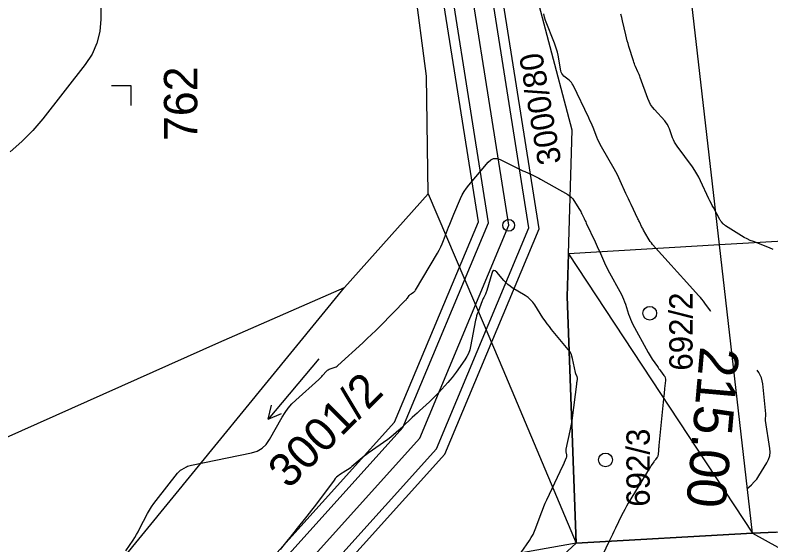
# Model space of a CAD drawing. Extents: x -534481 to -534262, y -1190577 to -1190138.
# Drawn here: x -534403.93 to -534384.66, y -1190505.1 to -1190491.61 of the extents above; entities that cross this region are included whole.
import ezdxf

# ---------------------------------------------------------------- set-up
doc = ezdxf.new("R2010")
doc.units = 0
for name, color, linetype in [('Bonity', 7, 'Continuous'), ('Definiční body', 7, 'Continuous'), ('Polygon budovy', 7, 'Continuous'), ('Polygon parcely', 7, 'Continuous'), ('Vrstva 17', 7, 'Continuous'), ('Vrstva 18', 7, 'Continuous'), ('Vrstva 19', 7, 'Continuous'), ('Vrstva 35', 7, 'Continuous'), ('Vrstva 37', 7, 'Continuous'), ('Vrstva 46', 7, 'Continuous'), ('Vrstva 48', 7, 'Continuous')]:
    doc.layers.add(name, color=color, linetype=linetype)

msp = doc.modelspace()

# ---------------------------------------------------------------- linework, layer by layer
at = {"layer": 'Bonity'}
msp.add_lwpolyline([(-534408.105, -1190518.46), (-534393.616, -1190502.389), (-534391.346, -1190496.962), (-534392.763, -1190488.017), (-534396.655, -1190477.752), (-534402.513, -1190464.283), (-534404.757, -1190456.741), (-534408.311, -1190433.088), (-534409.248, -1190427.879), (-534409.316, -1190416.054), (-534409.076, -1190409.418), (-534409.868, -1190391.439)], dxfattribs=at)
at = {"layer": 'Definiční body'}
for p, q in [((-534395.53, -1190498.55), (-534393.4, -1190496.16)), ((-534389.82, -1190497.69), (-534385.13, -1190504.81)), ((-534402.95, -1190507.61), (-534395.53, -1190498.55)), ((-534385.13, -1190504.81), (-534389.63, -1190505.06)), ((-534384.53, -1190504.78), (-534385.13, -1190504.81)), ((-534389.63, -1190505.06), (-534401.56, -1190515.98))]:
    msp.add_line(p, q, dxfattribs=at)
for points in [[(-534385.13, -1190504.81), (-534385.97, -1190497.46), (-534387.18, -1190486.94)], [(-534389.82, -1190497.69), (-534389.73, -1190494.54), (-534391.64, -1190487.29)], [(-534393.4, -1190496.16), (-534393.44, -1190493.16), (-534393.76, -1190490.76)], [(-534393.4, -1190496.16), (-534392, -1190499.45), (-534391.5, -1190500.63), (-534389.63, -1190505.06)], [(-534389.63, -1190505.06), (-534389.86, -1190498.78), (-534389.82, -1190497.69)], [(-534404.16, -1190502.37), (-534398.74, -1190499.95), (-534395.53, -1190498.55)], [(-534385.13, -1190504.81), (-534384.49, -1190505.16), (-534382.4, -1190506.3), (-534375.507, -1190510.084)], [(-534389.63, -1190505.06), (-534396.5, -1190506.28), (-534398.08, -1190506.56), (-534402.44, -1190507.34), (-534402.95, -1190507.61)]]:
    msp.add_lwpolyline(points, dxfattribs=at)
at = {"layer": 'Polygon parcely'}
msp.add_lwpolyline([(-534381.11, -1190486.74), (-534379.63, -1190494.14), (-534379.04, -1190497.06), (-534379.33, -1190497.08), (-534385.97, -1190497.46), (-534389.82, -1190497.69), (-534389.86, -1190498.78), (-534389.63, -1190505.06), (-534385.13, -1190504.81), (-534384.53, -1190504.78), (-534372.8, -1190504.12), (-534374.01, -1190497.07), (-534374.08, -1190496.69), (-534374.94, -1190492.52), (-534375.06, -1190491.94), (-534376.48, -1190486.28), (-534380.38, -1190486.72)], close=True, dxfattribs=at)
at = {"layer": 'Vrstva 18'}
for points in [[(-534384.605, -1190497.576), (-534384.698, -1190497.535), (-534385.11, -1190497.378), (-534385.189, -1190497.346), (-534385.267, -1190497.31), (-534385.342, -1190497.27), (-534385.416, -1190497.226), (-534385.821, -1190496.973), (-534385.836, -1190496.962), (-534385.85, -1190496.951), (-534385.864, -1190496.939), (-534385.876, -1190496.926), (-534385.925, -1190496.872), (-534385.937, -1190496.858), (-534385.947, -1190496.843), (-534385.957, -1190496.828), (-534385.966, -1190496.812), (-534386.129, -1190496.51), (-534386.159, -1190496.454), (-534386.188, -1190496.397), (-534386.216, -1190496.341), (-534386.243, -1190496.283), (-534386.454, -1190495.832), (-534386.5, -1190495.739), (-534386.551, -1190495.649), (-534386.606, -1190495.561), (-534386.665, -1190495.476), (-534387.056, -1190494.942), (-534387.09, -1190494.892), (-534387.12, -1190494.84), (-534387.146, -1190494.787), (-534387.168, -1190494.731), (-534387.249, -1190494.504), (-534387.272, -1190494.449), (-534387.299, -1190494.397), (-534387.332, -1190494.348), (-534387.37, -1190494.302), (-534387.63, -1190494.015), (-534387.683, -1190493.95), (-534387.729, -1190493.881), (-534387.768, -1190493.808), (-534387.801, -1190493.73), (-534387.995, -1190493.194), (-534388.008, -1190493.158), (-534388.022, -1190493.123), (-534388.037, -1190493.088), (-534388.052, -1190493.053), (-534388.114, -1190492.914), (-534388.13, -1190492.879), (-534388.144, -1190492.844), (-534388.156, -1190492.808), (-534388.168, -1190492.772), (-534388.282, -1190492.406), (-534388.304, -1190492.333), (-534388.325, -1190492.259), (-534388.344, -1190492.185), (-534388.362, -1190492.11), (-534388.443, -1190491.752), (-534388.464, -1190491.668), (-534388.488, -1190491.585)], [(-534401.104, -1190505.256), (-534400.924, -1190504.982), (-534400.88, -1190504.913), (-534400.838, -1190504.842), (-534400.797, -1190504.771), (-534400.758, -1190504.699), (-534400.552, -1190504.308), (-534400.504, -1190504.22), (-534400.451, -1190504.134), (-534400.394, -1190504.051), (-534400.334, -1190503.97), (-534399.786, -1190503.274), (-534399.763, -1190503.248), (-534399.739, -1190503.225), (-534399.712, -1190503.204), (-534399.683, -1190503.186), (-534399.563, -1190503.118), (-534399.533, -1190503.102), (-534399.502, -1190503.089), (-534399.469, -1190503.079), (-534399.436, -1190503.07), (-534397.901, -1190502.759), (-534397.758, -1190502.714), (-534397.633, -1190502.644), (-534397.528, -1190502.547), (-534397.442, -1190502.423), (-534397.122, -1190501.852), (-534397.048, -1190501.732), (-534396.965, -1190501.619), (-534396.873, -1190501.513), (-534396.772, -1190501.415), (-534396.19, -1190500.891), (-534396.165, -1190500.868), (-534396.14, -1190500.843), (-534396.115, -1190500.818), (-534396.092, -1190500.792), (-534395.989, -1190500.676), (-534395.969, -1190500.657), (-534395.948, -1190500.642), (-534395.925, -1190500.629), (-534395.9, -1190500.62), (-534395.795, -1190500.588), (-534395.77, -1190500.579), (-534395.746, -1190500.567), (-534395.724, -1190500.552), (-534395.703, -1190500.535), (-534395.065, -1190499.954), (-534394.953, -1190499.85), (-534394.842, -1190499.745), (-534394.733, -1190499.638), (-534394.625, -1190499.53), (-534393.978, -1190498.871), (-534393.965, -1190498.858), (-534393.952, -1190498.844), (-534393.941, -1190498.829), (-534393.929, -1190498.815), (-534393.883, -1190498.754), (-534393.872, -1190498.741), (-534393.86, -1190498.728), (-534393.846, -1190498.717), (-534393.832, -1190498.707), (-534393.773, -1190498.668), (-534393.759, -1190498.657), (-534393.746, -1190498.646), (-534393.735, -1190498.632), (-534393.725, -1190498.618), (-534393.164, -1190497.67), (-534393.12, -1190497.592), (-534393.079, -1190497.512), (-534393.042, -1190497.431), (-534393.009, -1190497.348), (-534392.882, -1190497.012), (-534392.85, -1190496.929), (-534392.816, -1190496.845), (-534392.782, -1190496.762), (-534392.748, -1190496.68), (-534392.576, -1190496.28), (-534392.533, -1190496.188), (-534392.483, -1190496.1), (-534392.426, -1190496.016), (-534392.363, -1190495.936), (-534391.869, -1190495.353), (-534391.803, -1190495.293), (-534391.731, -1190495.262), (-534391.652, -1190495.261), (-534391.568, -1190495.289), (-534391.142, -1190495.497), (-534391.091, -1190495.522), (-534391.041, -1190495.546), (-534390.99, -1190495.57), (-534390.938, -1190495.593), (-534390.733, -1190495.686), (-534390.682, -1190495.709), (-534390.632, -1190495.734), (-534390.582, -1190495.76), (-534390.533, -1190495.787), (-534389.84, -1190496.179), (-534389.794, -1190496.209), (-534389.753, -1190496.244), (-534389.716, -1190496.284), (-534389.685, -1190496.328), (-534389.544, -1190496.557), (-534389.528, -1190496.585), (-534389.512, -1190496.613), (-534389.497, -1190496.641), (-534389.482, -1190496.67), (-534389.426, -1190496.786), (-534389.412, -1190496.815), (-534389.398, -1190496.845), (-534389.384, -1190496.874), (-534389.37, -1190496.903), (-534389.145, -1190497.38), (-534389.117, -1190497.439), (-534389.09, -1190497.499), (-534389.063, -1190497.559), (-534389.036, -1190497.619), (-534388.931, -1190497.86), (-534388.905, -1190497.92), (-534388.876, -1190497.979), (-534388.847, -1190498.038), (-534388.816, -1190498.096), (-534388.475, -1190498.727), (-534388.445, -1190498.787), (-534388.418, -1190498.847), (-534388.393, -1190498.909), (-534388.372, -1190498.972), (-534388.291, -1190499.226), (-534388.27, -1190499.288), (-534388.245, -1190499.35), (-534388.218, -1190499.411), (-534388.188, -1190499.47), (-534387.79, -1190500.206), (-534387.766, -1190500.249), (-534387.741, -1190500.291), (-534387.714, -1190500.333), (-534387.686, -1190500.374), (-534387.557, -1190500.559), (-534387.536, -1190500.588), (-534387.516, -1190500.617), (-534387.495, -1190500.646), (-534387.474, -1190500.674), (-534387.389, -1190500.788), (-534387.371, -1190500.817), (-534387.359, -1190500.848), (-534387.353, -1190500.881), (-534387.353, -1190500.915), (-534387.372, -1190501.117), (-534387.376, -1190501.162), (-534387.38, -1190501.207), (-534387.385, -1190501.253), (-534387.389, -1190501.298), (-534387.518, -1190502.57), (-534387.52, -1190502.597), (-534387.523, -1190502.625), (-534387.526, -1190502.652), (-534387.528, -1190502.68), (-534387.54, -1190502.809), (-534387.543, -1190502.826), (-534387.548, -1190502.843), (-534387.555, -1190502.859), (-534387.565, -1190502.873), (-534387.607, -1190502.931), (-534387.617, -1190502.946), (-534387.627, -1190502.96), (-534387.638, -1190502.975), (-534387.648, -1190502.989), (-534387.714, -1190503.083), (-534387.728, -1190503.104), (-534387.742, -1190503.125), (-534387.756, -1190503.146), (-534387.769, -1190503.167), (-534388.298, -1190504.043), (-534388.343, -1190504.12), (-534388.387, -1190504.199), (-534388.429, -1190504.278), (-534388.469, -1190504.359), (-534388.625, -1190504.683), (-534388.664, -1190504.764), (-534388.703, -1190504.844), (-534388.743, -1190504.925), (-534388.782, -1190505.006), (-534388.96, -1190505.368)]]:
    msp.add_lwpolyline(points, dxfattribs=at)
at = {"layer": 'Vrstva 19'}
for points in [[(-534401.743, -1190490.295), (-534401.743, -1190491.711), (-534401.768, -1190492.026), (-534401.843, -1190492.324), (-534401.968, -1190492.605), (-534402.143, -1190492.868), (-534403.221, -1190494.245), (-534403.478, -1190494.548), (-534403.756, -1190494.829), (-534404.054, -1190495.088)], [(-534386.196, -1190499.156), (-534386.207, -1190499.14), (-534386.347, -1190498.943), (-534386.382, -1190498.894), (-534386.42, -1190498.847), (-534386.458, -1190498.801), (-534386.498, -1190498.755), (-534386.892, -1190498.325), (-534386.971, -1190498.238), (-534387.05, -1190498.151), (-534387.128, -1190498.064), (-534387.207, -1190497.977), (-534387.678, -1190497.449), (-534387.71, -1190497.412), (-534387.739, -1190497.374), (-534387.766, -1190497.334), (-534387.791, -1190497.292), (-534387.91, -1190497.084), (-534387.923, -1190497.061), (-534387.936, -1190497.037), (-534387.948, -1190497.014), (-534387.959, -1190496.99), (-534388.005, -1190496.893), (-534388.016, -1190496.869), (-534388.028, -1190496.845), (-534388.04, -1190496.82), (-534388.051, -1190496.796), (-534388.229, -1190496.429), (-534388.263, -1190496.36), (-534388.295, -1190496.29), (-534388.327, -1190496.22), (-534388.359, -1190496.15), (-534388.502, -1190495.826), (-534388.537, -1190495.749), (-534388.574, -1190495.673), (-534388.613, -1190495.599), (-534388.655, -1190495.525), (-534388.981, -1190494.96), (-534389.014, -1190494.902), (-534389.044, -1190494.842), (-534389.072, -1190494.782), (-534389.098, -1190494.72), (-534389.197, -1190494.472), (-534389.222, -1190494.41), (-534389.248, -1190494.348), (-534389.276, -1190494.288), (-534389.304, -1190494.227), (-534389.706, -1190493.394), (-534389.727, -1190493.358), (-534389.75, -1190493.324), (-534389.777, -1190493.293), (-534389.808, -1190493.265), (-534389.938, -1190493.158), (-534389.967, -1190493.129), (-534389.991, -1190493.097), (-534390.007, -1190493.061), (-534390.018, -1190493.022), (-534390.09, -1190492.627), (-534390.106, -1190492.549), (-534390.127, -1190492.471), (-534390.151, -1190492.394), (-534390.178, -1190492.318), (-534390.405, -1190491.744), (-534390.433, -1190491.658), (-534390.451, -1190491.57)], [(-534391.031, -1190505.3), (-534390.821, -1190504.996), (-534390.771, -1190504.919), (-534390.726, -1190504.839), (-534390.687, -1190504.756), (-534390.653, -1190504.671), (-534390.523, -1190504.308), (-534390.489, -1190504.219), (-534390.454, -1190504.131), (-534390.417, -1190504.044), (-534390.377, -1190503.958), (-534389.966, -1190503.093), (-534389.954, -1190503.068), (-534389.943, -1190503.044), (-534389.932, -1190503.019), (-534389.921, -1190502.994), (-534389.872, -1190502.879), (-534389.866, -1190502.862), (-534389.863, -1190502.844), (-534389.863, -1190502.826), (-534389.865, -1190502.808), (-534389.881, -1190502.735), (-534389.884, -1190502.717), (-534389.885, -1190502.699), (-534389.884, -1190502.68), (-534389.881, -1190502.662), (-534389.78, -1190502.2), (-534389.762, -1190502.117), (-534389.747, -1190502.033), (-534389.733, -1190501.949), (-534389.722, -1190501.865), (-534389.613, -1190501.013), (-534389.61, -1190500.996), (-534389.608, -1190500.979), (-534389.607, -1190500.962), (-534389.605, -1190500.946), (-534389.597, -1190500.873), (-534389.596, -1190500.859), (-534389.597, -1190500.845), (-534389.6, -1190500.832), (-534389.605, -1190500.819), (-534389.628, -1190500.767), (-534389.634, -1190500.754), (-534389.638, -1190500.741), (-534389.642, -1190500.727), (-534389.645, -1190500.713), (-534389.717, -1190500.355), (-534389.734, -1190500.292), (-534389.758, -1190500.233), (-534389.789, -1190500.178), (-534389.827, -1190500.126), (-534390.252, -1190499.617), (-534390.311, -1190499.544), (-534390.367, -1190499.47), (-534390.421, -1190499.394), (-534390.473, -1190499.316), (-534390.682, -1190498.992), (-534390.733, -1190498.922), (-534390.79, -1190498.858), (-534390.855, -1190498.802), (-534390.927, -1190498.753), (-534391.256, -1190498.551), (-534391.314, -1190498.512), (-534391.369, -1190498.469), (-534391.42, -1190498.422), (-534391.468, -1190498.371), (-534391.651, -1190498.16), (-534391.694, -1190498.122), (-534391.73, -1190498.114), (-534391.759, -1190498.136), (-534391.781, -1190498.189), (-534391.904, -1190498.623), (-534391.911, -1190498.646), (-534391.92, -1190498.669), (-534391.929, -1190498.692), (-534391.94, -1190498.714), (-534391.985, -1190498.801), (-534391.996, -1190498.823), (-534392.006, -1190498.845), (-534392.016, -1190498.868), (-534392.025, -1190498.89), (-534392.129, -1190499.164), (-534392.148, -1190499.218), (-534392.165, -1190499.272), (-534392.179, -1190499.327), (-534392.191, -1190499.383), (-534392.319, -1190500.049), (-534392.341, -1190500.139), (-534392.373, -1190500.225), (-534392.413, -1190500.308), (-534392.463, -1190500.386), (-534392.689, -1190500.706), (-534392.739, -1190500.775), (-534392.791, -1190500.841), (-534392.844, -1190500.907), (-534392.9, -1190500.97), (-534393.127, -1190501.222), (-534393.184, -1190501.284), (-534393.243, -1190501.344), (-534393.304, -1190501.404), (-534393.366, -1190501.461), (-534393.617, -1190501.688), (-534393.68, -1190501.745), (-534393.742, -1190501.802), (-534393.804, -1190501.86), (-534393.866, -1190501.918), (-534394.144, -1190502.182), (-534394.212, -1190502.245), (-534394.282, -1190502.304), (-534394.355, -1190502.361), (-534394.429, -1190502.416), (-534394.933, -1190502.772), (-534394.984, -1190502.809), (-534395.033, -1190502.847), (-534395.082, -1190502.886), (-534395.13, -1190502.926), (-534395.343, -1190503.109), (-534395.38, -1190503.139), (-534395.418, -1190503.169), (-534395.458, -1190503.196), (-534395.498, -1190503.222), (-534395.661, -1190503.324), (-534395.701, -1190503.351), (-534395.737, -1190503.381), (-534395.77, -1190503.415), (-534395.8, -1190503.452), (-534396.25, -1190504.057), (-534396.31, -1190504.137), (-534396.371, -1190504.217), (-534396.432, -1190504.296), (-534396.494, -1190504.375), (-534396.771, -1190504.723), (-534396.82, -1190504.784), (-534396.869, -1190504.844), (-534396.917, -1190504.905), (-534396.966, -1190504.966), (-534397.175, -1190505.224)], [(-534385.279, -1190503.674), (-534385.229, -1190503.635), (-534385.154, -1190503.572), (-534385.087, -1190503.502), (-534385.025, -1190503.427), (-534384.97, -1190503.347), (-534384.764, -1190503.012), (-534384.72, -1190502.926), (-534384.694, -1190502.838), (-534384.684, -1190502.746), (-534384.69, -1190502.65), (-534384.801, -1190501.935), (-534384.803, -1190501.921), (-534384.803, -1190501.907), (-534384.803, -1190501.893), (-534384.802, -1190501.879), (-534384.796, -1190501.822), (-534384.795, -1190501.808), (-534384.795, -1190501.794), (-534384.795, -1190501.78), (-534384.796, -1190501.766), (-534384.871, -1190500.998), (-534384.883, -1190500.923), (-534384.904, -1190500.851), (-534384.933, -1190500.782), (-534384.972, -1190500.716), (-534385.011, -1190500.656)]]:
    msp.add_lwpolyline(points, dxfattribs=at)
at = {"layer": 'Vrstva 35'}
for points in [[(-534405.407, -1190514.348), (-534394.258, -1190501.982), (-534392.12, -1190496.869), (-534393.492, -1190488.211), (-534397.35, -1190478.035), (-534403.219, -1190464.54), (-534405.491, -1190456.905), (-534409.051, -1190433.21), (-534409.998, -1190427.948), (-534410.066, -1190416.042), (-534409.827, -1190409.421), (-534410.645, -1190390.84)], [(-534405.057, -1190514.333), (-534394.044, -1190502.118), (-534391.862, -1190496.9), (-534393.249, -1190488.146), (-534397.118, -1190477.94), (-534402.983, -1190464.455), (-534405.247, -1190456.85), (-534408.804, -1190433.17), (-534409.748, -1190427.925), (-534409.816, -1190416.046), (-534409.577, -1190409.42), (-534410.397, -1190390.795)], [(-534403.656, -1190514.273), (-534393.187, -1190502.661), (-534390.83, -1190497.024), (-534392.278, -1190487.888), (-534396.191, -1190477.563), (-534402.042, -1190464.111), (-534404.268, -1190456.632), (-534407.818, -1190433.007), (-534408.749, -1190427.833), (-534408.816, -1190416.061), (-534408.576, -1190409.416), (-534409.363, -1190391.537)], [(-534403.306, -1190514.257), (-534392.973, -1190502.796), (-534390.572, -1190497.055), (-534392.035, -1190487.824), (-534395.96, -1190477.469), (-534401.807, -1190464.025), (-534404.023, -1190456.578), (-534407.571, -1190432.966), (-534408.499, -1190427.81), (-534408.566, -1190416.065), (-534408.326, -1190409.415), (-534409.111, -1190391.586)]]:
    msp.add_lwpolyline(points, dxfattribs=at)
at = {"layer": 'Vrstva 37'}
msp.add_circle((-534391.346, -1190496.962), 0.15, dxfattribs=at)
msp.add_circle((-534391.346, -1190496.962), 0.15, dxfattribs=at)
msp.add_circle((-534391.346, -1190496.962), 0.15, dxfattribs=at)
msp.add_circle((-534391.346, -1190496.962), 0.15, dxfattribs=at)
msp.add_circle((-534391.346, -1190496.962), 0.15, dxfattribs=at)
msp.add_circle((-534391.346, -1190496.962), 0.15, dxfattribs=at)
at = {"layer": 'Vrstva 46'}
for centre in [(-534387.753, -1190499.204), (-534388.88, -1190502.94)]:
    msp.add_circle(centre, 0.175, dxfattribs=at)
at = {"layer": 'Vrstva 48'}
for p, q in [((-534400.971, -1190493.411), (-534401.471, -1190493.411)), ((-534400.971, -1190493.911), (-534400.971, -1190493.411)), ((-534396.186, -1190500.362), (-534397.478, -1190501.902)), ((-534397.478, -1190501.902), (-534397.396, -1190501.543)), ((-534397.478, -1190501.902), (-534397.139, -1190501.759))]:
    msp.add_line(p, q, dxfattribs=at)

# ---------------------------------------------------------------- texts
at = {"layer": 'Polygon budovy'}
for s, height, rotation, p in [('3000/80', 0.595, 100, (-534390.001, -1190495.363)), ('762', 0.85, 90, (-534399.286, -1190494.813)), ('692/2', 0.595, 90, (-534386.659, -1190500.665)), ('3001/2', 0.85, 45, (-534396.959, -1190503.703)), ('692/3', 0.595, 90, (-534387.751, -1190504.133))]:
    msp.add_text(s, height=height, rotation=rotation, dxfattribs=at).set_placement(p)
at = {"layer": 'Vrstva 17'}
msp.add_text('215.00', height=1, rotation=264.9313, dxfattribs=at).set_placement((-534386.462, -1190500.034))

doc.saveas('drawing.dxf')
